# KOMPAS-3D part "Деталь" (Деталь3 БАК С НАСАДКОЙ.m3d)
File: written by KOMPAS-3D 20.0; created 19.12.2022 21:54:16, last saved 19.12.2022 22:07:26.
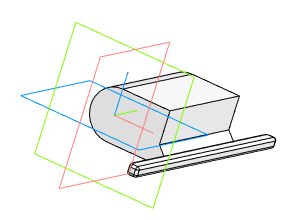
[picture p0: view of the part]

Document properties: Полное имя файла: C:\Users\Семья\Desktop\ДЕТАЛИ ДЛЯ СБОРЩИКА БОРЩЕВИКА\ДЕТАЛИ ДЛЯ ФИНАЛА\Деталь3 БАК С НАСАДКОЙ.m3d

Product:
- Part/product: Деталь
    Масса: 0.238396

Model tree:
1. Эскиз:1
2. Элемент выдавливания:2
     Расстояние 1 = 50
3. Эскиз:5  (with: Элемент выдавливания:2)
4. Элемент выдавливания:6
     Расстояние 1 = 3
5. Эскиз:6  (with: Элемент выдавливания:2, Элемент выдавливания:6)
6. Элемент выдавливания:7
     Расстояние 2 = 50
7. Эскиз:7  (with: Элемент выдавливания:6)
8. Элемент выдавливания:8
     Расстояние 1 = 4
9. Скругление:7  (with: Элемент выдавливания:8)
     Радиус = 1
10. Скругление:8  (with: Элемент выдавливания:8)
     Радиус = 1
11. Скругление:9  (with: Элемент выдавливания:8)
     Радиус = 1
